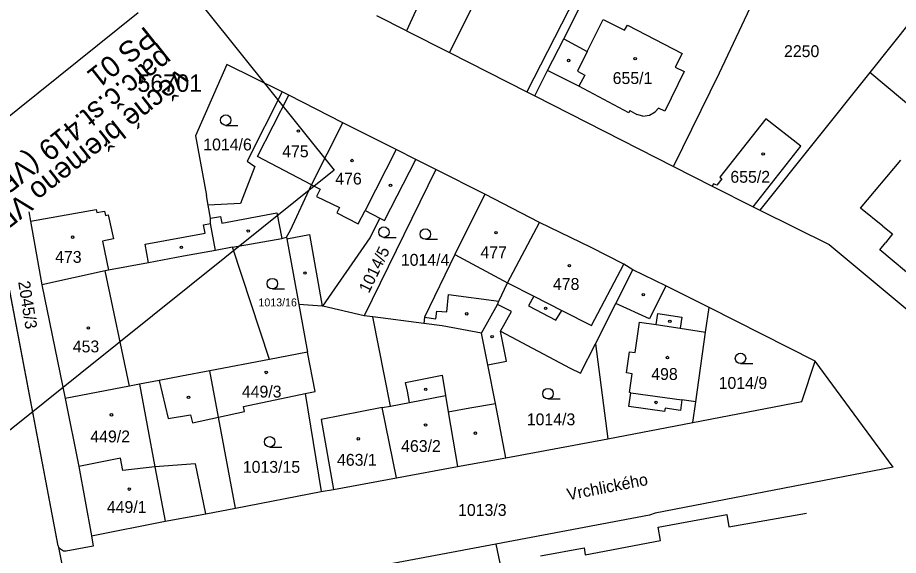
# Model space of a CAD drawing. Extents: x -794765 to -785424, y -1118958 to -1108731.
# Drawn here: x -791983.5 to -791857.2, y -1109797.6 to -1109720.5 of the extents above; entities that cross this region are included whole.
import ezdxf

# ---------------------------------------------------------------- set-up
doc = ezdxf.new("R2010")
doc.units = 0
for name, color, linetype in [('Level 66', 7, 'Continuous'), ('Level 71', 7, 'Continuous'), ('Level 75', 7, 'Continuous'), ('Level 76', 7, 'Continuous'), ('Level 77', 7, 'Continuous'), ('Level 79', 7, 'Continuous'), ('Level 80', 7, 'Continuous'), ('Level 81', 7, 'Continuous'), ('Vrstva 1', 7, 'Continuous')]:
    doc.layers.add(name, color=color, linetype=linetype)

msp = doc.modelspace()

# ---------------------------------------------------------------- linework, layer by layer
at = {"layer": 'Level 66'}
for p, q in [((-791953.64, -1109735.96), (-791951.89, -1109735.96)), ((-791930.97, -1109752.01), (-791929.22, -1109752.01)), ((-791925.03, -1109752.29), (-791923.28, -1109752.29)), ((-791946.96, -1109759.39), (-791945.21, -1109759.39)), ((-791879.86, -1109770.1), (-791878.11, -1109770.1)), ((-791907.45, -1109775.16), (-791905.7, -1109775.16)), ((-791947.34, -1109782.06), (-791945.59, -1109782.06))]:
    msp.add_line(p, q, dxfattribs=at)
for centre in [(-791953.64, -1109735.21), (-791930.97, -1109751.26), (-791925.03, -1109751.54), (-791946.96, -1109758.64), (-791879.86, -1109769.35), (-791907.45, -1109774.41), (-791947.34, -1109781.31)]:
    msp.add_circle(centre, 0.75, dxfattribs=at)
at = {"layer": 'Level 71'}
msp.add_lwpolyline([(-791938.08, -1109742.36), (-792598.01, -1110271.46), (-792786.15, -1110036.8), (-792126.22, -1109507.7)], close=True, dxfattribs=at)
at = {"layer": 'Level 75'}
for p, q in [((-791927.74, -1109722.4), (-791931.97, -1109720.25)), ((-791855.28, -1109720.85), (-791861.3, -1109728.39)), ((-791953.47, -1109727.24), (-791957.98, -1109737.48)), ((-791945.56, -1109731.16), (-791953.47, -1109727.24)), ((-791861.3, -1109728.39), (-791877.07, -1109748.13)), ((-791837.39, -1109748.55), (-791861.3, -1109728.39)), ((-791909.36, -1109731.72), (-791889.45, -1109741.84)), ((-791957.98, -1109737.48), (-791956.42, -1109746.03)), ((-791923.52, -1109742.28), (-791926.4, -1109740.83)), ((-791923.52, -1109742.28), (-791933.8, -1109763.25)), ((-791916.48, -1109745.84), (-791923.52, -1109742.28)), ((-791889.45, -1109741.84), (-791883.9, -1109744.66)), ((-791883.9, -1109744.66), (-791878.03, -1109747.64)), ((-791956.17, -1109747.38), (-791956.42, -1109746.03)), ((-791908.66, -1109749.89), (-791916.48, -1109745.84)), ((-791878.03, -1109747.64), (-791877.07, -1109748.13)), ((-791977.67, -1109796.24), (-791985.8, -1109753.42)), ((-791952.67, -1109753.41), (-791955.12, -1109753.87)), ((-791947.39, -1109769.52), (-791952.67, -1109753.41)), ((-791980, -1109758.8), (-791976.67, -1109775.1)), ((-791943.16, -1109761.65), (-791941.92, -1109768.48)), ((-791933.8, -1109763.25), (-791939.71, -1109761.86)), ((-791869.18, -1109769.73), (-791884.37, -1109762.08)), ((-791932.57, -1109763.41), (-791933.8, -1109763.25)), ((-791925.23, -1109764.37), (-791932.57, -1109763.41)), ((-791916.05, -1109770.26), (-791916.98, -1109765.74)), ((-791900.65, -1109767.25), (-791898.88, -1109780.87)), ((-791941.92, -1109768.48), (-791947.39, -1109769.52)), ((-791947.39, -1109769.52), (-791955.94, -1109771.15)), ((-791858, -1109784.94), (-791869.18, -1109769.73)), ((-791954.7, -1109777.79), (-791955.94, -1109771.15)), ((-791976.67, -1109775.1), (-791974.7, -1109784.87)), ((-791942.26, -1109774.38), (-791939.94, -1109788.43)), ((-791952.26, -1109790.84), (-791954.7, -1109777.79)), ((-791898.88, -1109780.87), (-791886.67, -1109778.56)), ((-791913.48, -1109783.61), (-791898.88, -1109780.87)), ((-791974.7, -1109784.87), (-791972.9, -1109794.78)), ((-791952.26, -1109790.84), (-791939.94, -1109788.43)), ((-791956.49, -1109791.62), (-791952.26, -1109790.84)), ((-791977.67, -1109796.24), (-791975.55, -1109806.82)), ((-791914.93, -1109795.98), (-791934.5, -1109799.64)), ((-791914.93, -1109795.98), (-791910.09, -1109818.33))]:
    msp.add_line(p, q, dxfattribs=at)
for points in [[(-791909.43, -1109693.51), (-791921.58, -1109715.65), (-791924.01, -1109714.23), (-791927.74, -1109722.4)], [(-791909.36, -1109731.72), (-791907.51, -1109728.09), (-791905.2, -1109723.56), (-791896.25, -1109705.77)], [(-791889.45, -1109741.84), (-791882.86, -1109728.42), (-791877.68, -1109717.35)], [(-791927.74, -1109722.4), (-791921.59, -1109725.52), (-791910.47, -1109731.16), (-791909.36, -1109731.72)], [(-791945.56, -1109731.16), (-791950.56, -1109741.08), (-791949.46, -1109741.85), (-791951.52, -1109747.16), (-791956.17, -1109747.38)], [(-791936.85, -1109735.6), (-791944.59, -1109731.64), (-791945.56, -1109731.16)], [(-791944.92, -1109751.98), (-791944.35, -1109750.98), (-791941.37, -1109744.5), (-791936.85, -1109735.6)], [(-791926.4, -1109740.83), (-791929.2, -1109739.43), (-791936.85, -1109735.6)], [(-791878.03, -1109747.64), (-791871.19, -1109738.94), (-791876.22, -1109735.02), (-791882.82, -1109743.38), (-791882.54, -1109743.62), (-791883.25, -1109744.54), (-791883.73, -1109744.32), (-791883.9, -1109744.66)], [(-791939.71, -1109761.86), (-791932.93, -1109752.07), (-791931.53, -1109749.25), (-791930.88, -1109749.58), (-791926.4, -1109740.83)], [(-791916.48, -1109745.84), (-791920.82, -1109754.46), (-791925.16, -1109763.43), (-791925.23, -1109764.37)], [(-791981.88, -1109748.34), (-791981.62, -1109749.67), (-791980, -1109758.8)], [(-791955.12, -1109753.87), (-791955.83, -1109750.03), (-791955.83, -1109749.27), (-791956.17, -1109747.38)], [(-791877.07, -1109748.13), (-791867.13, -1109753.04), (-791851.69, -1109765.91)], [(-791916.98, -1109765.74), (-791914.7, -1109761.63), (-791914.48, -1109761.17), (-791913.24, -1109758.52), (-791908.66, -1109749.89)], [(-791895.28, -1109756.65), (-791896.56, -1109755.87), (-791901.25, -1109753.47), (-791908.66, -1109749.89)], [(-791952.67, -1109753.41), (-791945.6, -1109752.19), (-791944.92, -1109751.98)], [(-791944.92, -1109751.98), (-791944.88, -1109752.2), (-791943.16, -1109761.65)], [(-791955.12, -1109753.87), (-791959.71, -1109754.71), (-791964.71, -1109755.64), (-791970.45, -1109756.7), (-791970.94, -1109756.81), (-791980, -1109758.8)], [(-791900.65, -1109767.25), (-791897.74, -1109761.51), (-791895.28, -1109756.65)], [(-791884.37, -1109762.08), (-791890.57, -1109758.96), (-791895.28, -1109756.65)], [(-791939.71, -1109761.86), (-791939.81, -1109761.85), (-791943.16, -1109761.65)], [(-791886.67, -1109778.56), (-791886.25, -1109775.56), (-791884.86, -1109765.59), (-791884.37, -1109762.08)], [(-791929.16, -1109786.47), (-791931.21, -1109776.4), (-791930.04, -1109776.18), (-791932.57, -1109763.41)], [(-791916.98, -1109765.74), (-791922.61, -1109764.71), (-791925.23, -1109764.37)], [(-791916.05, -1109770.26), (-791913.4, -1109769.73), (-791914.24, -1109765.44), (-791904.26, -1109770.74), (-791902.77, -1109771.45), (-791900.65, -1109767.25)], [(-791942.26, -1109774.38), (-791940.83, -1109774.08), (-791941.92, -1109768.48)], [(-791886.67, -1109778.56), (-791871.09, -1109775.55), (-791869.18, -1109769.73)], [(-791955.94, -1109771.15), (-791959.99, -1109771.92), (-791963.2, -1109772.53), (-791966.01, -1109773.07), (-791967.41, -1109773.34), (-791976.67, -1109775.1)], [(-791913.48, -1109783.61), (-791914.98, -1109775.8), (-791916.05, -1109770.26)], [(-791954.7, -1109777.79), (-791950.95, -1109776.97), (-791951.11, -1109776.23), (-791942.26, -1109774.38)], [(-791956.49, -1109791.62), (-791957.96, -1109784.45), (-791963.78, -1109784.91), (-791968.37, -1109785.42), (-791968.72, -1109783.66), (-791974.7, -1109784.87)], [(-791929.16, -1109786.47), (-791920.41, -1109784.85), (-791913.48, -1109783.61)], [(-791858, -1109784.94), (-791892.07, -1109791.53), (-791892.88, -1109791.84), (-791914.93, -1109795.98)], [(-791939.94, -1109788.43), (-791938.21, -1109788.12), (-791929.16, -1109786.47)], [(-791972.9, -1109794.78), (-791962.31, -1109792.7), (-791956.49, -1109791.62)], [(-791972.9, -1109794.78), (-791972.62, -1109796.28), (-791976.5, -1109797)], [(-791976.5, -1109797), (-791976.87, -1109796.96), (-791977.2, -1109796.81), (-791977.47, -1109796.58), (-791977.67, -1109796.24)]]:
    msp.add_lwpolyline(points, dxfattribs=at)
at = {"layer": 'Level 77'}
for p, q in [((-791921.59, -1109725.52), (-791910.47, -1109703.57)), ((-791899.3, -1109709.19), (-791910.47, -1109731.16)), ((-791901.82, -1109725.39), (-791899.54, -1109720.78)), ((-791899.54, -1109720.78), (-791896.48, -1109722.29)), ((-791896.48, -1109722.29), (-791896.05, -1109721.6)), ((-791896.05, -1109721.6), (-791888.22, -1109725.67)), ((-791905.2, -1109723.56), (-791901.82, -1109725.39)), ((-791901.82, -1109725.39), (-791903.21, -1109728.21)), ((-791888.22, -1109725.67), (-791889.23, -1109727.61)), ((-791903.01, -1109730.36), (-791907.51, -1109728.09)), ((-791903.21, -1109728.21), (-791902.16, -1109728.78)), ((-791902.16, -1109728.78), (-791903.01, -1109730.36)), ((-791949.07, -1109740.43), (-791944.59, -1109731.64)), ((-791895.7, -1109733.84), (-791894.73, -1109734.41)), ((-791893.84, -1109734.63), (-791894.73, -1109734.41)), ((-791893.84, -1109734.63), (-791892.89, -1109734.49)), ((-791892.89, -1109734.49), (-791892.11, -1109734.04)), ((-791891.63, -1109733.48), (-791892.11, -1109734.04)), ((-791890.7, -1109733.94), (-791891.63, -1109733.48)), ((-791929.2, -1109739.43), (-791933.67, -1109748.15)), ((-791941.37, -1109744.5), (-791949.07, -1109740.43)), ((-791862.67, -1109747.82), (-791856.87, -1109740.94)), ((-791941.37, -1109744.5), (-791940.11, -1109745.1)), ((-791940.11, -1109745.1), (-791940.62, -1109746.17)), ((-791940.62, -1109746.17), (-791937.33, -1109747.73)), ((-791981.62, -1109749.67), (-791972.2, -1109748)), ((-791972.2, -1109748), (-791972.11, -1109748.45)), ((-791972.11, -1109748.45), (-791971, -1109748.23)), ((-791971, -1109748.23), (-791970.87, -1109748.86)), ((-791954.21, -1109749.99), (-791946.32, -1109748.47)), ((-791946.32, -1109748.47), (-791945.6, -1109752.19)), ((-791937.33, -1109747.73), (-791937.7, -1109748.51)), ((-791937.7, -1109748.51), (-791934.65, -1109750.07)), ((-791934.65, -1109750.07), (-791933.67, -1109748.15)), ((-791933.67, -1109748.15), (-791931.53, -1109749.25)), ((-791859.45, -1109750.41), (-791862.67, -1109747.82)), ((-791970.87, -1109748.86), (-791970.47, -1109748.78)), ((-791970.47, -1109748.78), (-791969.73, -1109752.21)), ((-791955.83, -1109749.27), (-791954.4, -1109749.01)), ((-791954.4, -1109749.01), (-791954.21, -1109749.99)), ((-791956.82, -1109750.22), (-791955.83, -1109750.03)), ((-791956.61, -1109751.4), (-791956.82, -1109750.22)), ((-791859.45, -1109750.41), (-791858.06, -1109751.52)), ((-791969.73, -1109752.21), (-791971.29, -1109752.53)), ((-791965.21, -1109752.98), (-791956.61, -1109751.4)), ((-791944.88, -1109752.2), (-791941.65, -1109751.61)), ((-791941.65, -1109751.61), (-791939.81, -1109761.85)), ((-791858.06, -1109751.52), (-791859.07, -1109752.78)), ((-791971.29, -1109752.53), (-791970.45, -1109756.7)), ((-791964.71, -1109755.64), (-791965.21, -1109752.98)), ((-791859.87, -1109753.78), (-791859.07, -1109752.78)), ((-791920.82, -1109754.46), (-791913.24, -1109758.52)), ((-791852.28, -1109760.19), (-791859.87, -1109753.78)), ((-791901.21, -1109764.62), (-791896.56, -1109755.87)), ((-791967.41, -1109773.34), (-791970.94, -1109756.81)), ((-791913.24, -1109758.52), (-791909.5, -1109760.42)), ((-791890.57, -1109758.96), (-791892.91, -1109763.66)), ((-791921.94, -1109762.69), (-791921.7, -1109760.2)), ((-791921.7, -1109760.2), (-791914.48, -1109761.17)), ((-791909.5, -1109760.42), (-791910.25, -1109761.81)), ((-791909.5, -1109760.42), (-791905.47, -1109762.47)), ((-791912.7, -1109762.62), (-791914.7, -1109761.63)), ((-791910.25, -1109761.81), (-791906.34, -1109763.88)), ((-791906.34, -1109763.88), (-791905.47, -1109762.47)), ((-791905.47, -1109762.47), (-791901.21, -1109764.62)), ((-791892.91, -1109763.66), (-791897.74, -1109761.51)), ((-791925.16, -1109763.43), (-791923.53, -1109763.67)), ((-791923.53, -1109763.67), (-791923.38, -1109762.6)), ((-791923.38, -1109762.6), (-791921.94, -1109762.69)), ((-791914.24, -1109765.44), (-791912.7, -1109762.62)), ((-791891.93, -1109764.51), (-791891.69, -1109762.92)), ((-791891.69, -1109762.92), (-791888.25, -1109763.44)), ((-791888.25, -1109763.44), (-791888.49, -1109765.04)), ((-791894.95, -1109768.53), (-791894.33, -1109764.15)), ((-791894.33, -1109764.15), (-791891.93, -1109764.51)), ((-791891.93, -1109764.51), (-791888.49, -1109765.04)), ((-791888.49, -1109765.04), (-791884.86, -1109765.59)), ((-791896.2, -1109771.44), (-791895.77, -1109768.42)), ((-791895.77, -1109768.42), (-791894.95, -1109768.53)), ((-791963.2, -1109772.53), (-791961.89, -1109777.95)), ((-791927.86, -1109772.82), (-791922.63, -1109771.77)), ((-791922.63, -1109771.77), (-791922.14, -1109774.67)), ((-791895.38, -1109771.55), (-791896.2, -1109771.44)), ((-791895.77, -1109774.25), (-791895.38, -1109771.55)), ((-791966.01, -1109773.07), (-791963.78, -1109784.91)), ((-791927.61, -1109774.06), (-791927.86, -1109772.82)), ((-791927.32, -1109775.66), (-791927.61, -1109774.06)), ((-791927.32, -1109775.66), (-791922.14, -1109774.67)), ((-791922.14, -1109774.67), (-791921.74, -1109777.01)), ((-791895.85, -1109776.23), (-791895.58, -1109774.27)), ((-791895.58, -1109774.27), (-791895.77, -1109774.25)), ((-791895.58, -1109774.27), (-791888.26, -1109775.28)), ((-791930.04, -1109776.18), (-791927.32, -1109775.66)), ((-791918.63, -1109776.44), (-791914.98, -1109775.8)), ((-791890.73, -1109776.95), (-791895.85, -1109776.23)), ((-791888.26, -1109775.28), (-791888.47, -1109776.81)), ((-791886.25, -1109775.56), (-791888.26, -1109775.28)), ((-791961.89, -1109777.95), (-791958.69, -1109777.44)), ((-791958.69, -1109777.44), (-791958.41, -1109778.61)), ((-791931.21, -1109776.4), (-791939.98, -1109778.13)), ((-791921.74, -1109777.01), (-791918.63, -1109776.44)), ((-791921.74, -1109777.01), (-791920.41, -1109784.85)), ((-791890.66, -1109776.51), (-791890.73, -1109776.95)), ((-791888.47, -1109776.81), (-791890.66, -1109776.51)), ((-791958.41, -1109778.61), (-791954.7, -1109777.79)), ((-791939.98, -1109778.13), (-791938.21, -1109788.12)), ((-791963.78, -1109784.91), (-791962.31, -1109792.7)), ((-791881.51, -1109793.48), (-791870.39, -1109791.52)), ((-791891.67, -1109793.52), (-791881.84, -1109791.71)), ((-791881.84, -1109791.71), (-791881.51, -1109793.48)), ((-791891.31, -1109795.47), (-791891.67, -1109793.52)), ((-791908.53, -1109797.65), (-791902.29, -1109796.48)), ((-791902.29, -1109796.48), (-791902.1, -1109797.52)), ((-791902.1, -1109797.52), (-791891.31, -1109795.47))]:
    msp.add_line(p, q, dxfattribs=at)
for points in [[(-791889.23, -1109727.61), (-791887.92, -1109728.26), (-791890.7, -1109733.94)], [(-791895.7, -1109733.84), (-791895.88, -1109734.18), (-791903.01, -1109730.36)]]:
    msp.add_lwpolyline(points, dxfattribs=at)
at = {"layer": 'Level 79'}
for centre in [(-791904.5, -1109726.66), (-791894.96, -1109726.39), (-791943.22, -1109736.77), (-791935.53, -1109741), (-791876.61, -1109740.05), (-791930.02, -1109744.55), (-791950.42, -1109751.1), (-791975.58, -1109751.98), (-791914.9, -1109751.32), (-791959.99, -1109753.44), (-791904.39, -1109756.08), (-791942.29, -1109757.13), (-791893.8, -1109760.23), (-791907.79, -1109762.19), (-791919.1, -1109762.97), (-791973.32, -1109764.99), (-791889.99, -1109764.04), (-791915.46, -1109766.24), (-791890.33, -1109769.23), (-791947.84, -1109771.37), (-791924.97, -1109773.79), (-791958.98, -1109774.95), (-791891.97, -1109775.67), (-791970.02, -1109777.44), (-791925, -1109778.9), (-791917.85, -1109780.07), (-791934.65, -1109780.88), (-791967.46, -1109788.09)]:
    msp.add_circle(centre, 0.175, dxfattribs=at)
at = {"layer": 'Level 81'}
msp.add_lwpolyline([(-791977.67, -1109796.24), (-791991.98, -1109720.83), (-791992.2, -1109719.5), (-791992.26, -1109718.2), (-791992.18, -1109716.87), (-791991.97, -1109715.65), (-791991.56, -1109714.23), (-791990.95, -1109712.85), (-791990.23, -1109711.63), (-791989.17, -1109710.28), (-791986.99, -1109712.39), (-791985.69, -1109711.05), (-791974.78, -1109691.82), (-791964.15, -1109675.11), (-791952.08, -1109657.83), (-791949.02, -1109652.63), (-791945.89, -1109647.32), (-791945.08, -1109645.94)], dxfattribs=at)
at = {"layer": 'Vrstva 1'}
msp.add_line((-791966.17, -1109719.81), (-792028.19, -1109769.53), dxfattribs=at)

# ---------------------------------------------------------------- texts
at = {"layer": 'Level 76'}
for s, height, p in [('2250', 1.7, (-791873.62, -1109726.17)), ('655/1', 1.7, (-791898.18, -1109730.03)), ('1014/6', 1.7, (-791956.86, -1109739.55)), ('475', 1.7, (-791945.55, -1109740.53)), ('476', 1.7, (-791937.94, -1109744.44)), ('655/2', 1.7, (-791881.31, -1109744.18)), ('477', 1.7, (-791917.13, -1109754.99)), ('473', 1.7, (-791978.09, -1109755.66)), ('1014/4', 1.7, (-791928.54, -1109756.08)), ('478', 1.7, (-791906.74, -1109759.54)), ('1013/16', 1.14, (-791948.95, -1109761.9)), ('453', 1.7, (-791975.56, -1109768.49)), ('498', 1.7, (-791892.65, -1109772.44)), ('1014/9', 1.7, (-791882.99, -1109773.72)), ('449/3', 1.7, (-791951.33, -1109774.96)), ('1014/3', 1.7, (-791910.49, -1109778.94)), ('449/2', 1.7, (-791973.05, -1109781.39)), ('463/2', 1.7, (-791928.5, -1109782.76)), ('1013/15', 1.7, (-791951.19, -1109785.75)), ('463/1', 1.7, (-791937.69, -1109784.74)), ('449/1', 1.7, (-791970.68, -1109791.5)), ('1013/3', 1.7, (-791920.34, -1109791.93))]:
    msp.add_text(s, height=height, dxfattribs=at).set_placement(p)
for s, rotation, p in [('1014/5', 64, (-791933.12, -1109760.11)), ('2045/3', 279, (-791983.4, -1109758.38))]:
    msp.add_text(s, height=1.7, rotation=rotation, dxfattribs=at).set_placement(p)
at = {"layer": 'Level 80'}
msp.add_text('Vrchlického', height=1.7, rotation=11, dxfattribs=at).set_placement((-791904.56, -1109789.71))
at = {"layer": 'Level 81'}
msp.add_text('56701', height=2.5, dxfattribs=at).set_placement((-791966.31, -1109731.15))
at = {"layer": 'Vrstva 1'}
for s, p in [('PS 01', (-791965.16, -1109721.63)), ('parc.č.st.419 (VB se vztahuje jen na stavbu), 32m2', (-791962.75, -1109724.68)), ('věcné břemeno VB-01', (-791960.34, -1109727.72))]:
    msp.add_text(s, height=3, rotation=218.3254, dxfattribs=at).set_placement(p)

doc.saveas('drawing.dxf')
